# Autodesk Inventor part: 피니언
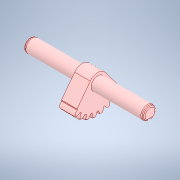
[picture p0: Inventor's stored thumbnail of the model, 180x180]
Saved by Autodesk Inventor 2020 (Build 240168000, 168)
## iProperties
Created: 2024-05
Part Number: 피니언
Material: 강철, 탄소
Document SubType Name: Modeling
Designer: oem
Density: 7.85 g/cm^3
Appearance: 기본값
Author: jhkim
Sending System: Autodesk Inventor 2025
Preprocessor: ST-DEVELOPER v20
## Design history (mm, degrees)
feature "솔리드1"
node "솔리드2"
